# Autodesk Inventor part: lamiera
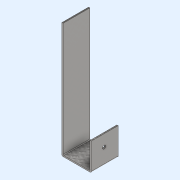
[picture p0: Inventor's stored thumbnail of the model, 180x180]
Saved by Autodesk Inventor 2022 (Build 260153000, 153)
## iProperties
Created: 2022-01
Part Number: lamiera
Material: Generico
Document SubType Name: Modeling
Designer: admin
Density: 1 g/cm^3
Appearance: Lamiera con rombi
Author: admin
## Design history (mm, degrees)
sketch "Schizzo1"
  geometry: L1 (-350, 190.785)-(-340, 200.785) reference; L2 (-350, 190.785)-(-350, -190.785) reference; L3 (-340, -200.785)-(-350, -190.785) reference; L4 (-340, -200.785)-(-290, -200.785) reference; L5 (-290, -200.785)-(-290, -100.323) reference; L6 (-290, -100.323)-(-265.5, -100.323) reference; L7 (-238.5, -73.323)-(-265.5, -100.323) reference; L8 (-238.5, -73.323)-(-238.5, 100.785) reference; L9 (-238.5, 100.785)-(-25, 100.785) reference; L10 (-25, 100.785)-(-25, -88.215) reference; L11 (-24, -89.215)-(14, -89.215) reference; L12 (15, -88.215)-(15, 25.785) reference; L13 (15, 25.785)-(90, 100.785) reference; L14 (90, 100.785)-(315, 100.785) reference; L15 (315, 100.785)-(315, -99.215) reference; L16 (315, -99.215)-(90, -99.215) reference; L17 (90, -99.215)-(90, -389.215) reference; L18 (100, -399.215)-(90, -389.215) reference; L19 (100, -399.215)-(350, -399.215) reference; L20 (350, -399.215)-(350, 200.785) reference; L21 (350, 200.785)-(-340, 200.785) reference; L22 (-25, 80.782)-(-25, -88.215); L23 (-24, -89.215)-(14, -89.215); L24 (15, -88.215)-(15, -50.215); L25 (17, -50.215)-(17, -89.218); L26 (15, -91.218)-(-25, -91.218); L27 (-27, -89.218)-(-27, 80.782); L28 (15, -38.215)-(17, -38.215); L29 (-27, 80.782)-(-25, 80.782); L30 (15, -50.215)-(17, -50.215); A1 r 1 centre (-24, -88.215) between (-25, -88.215) and (-24, -89.215) reference; A2 r 1 centre (14, -88.215) between (14, -89.215) and (15, -88.215) reference; A3 r 2 centre (-25, -89.218) between (-27, -89.218) and (-25, -91.218); A4 r 2 centre (15, -89.218) between (15, -91.218) and (17, -89.218); 1 further point
  constraints: 18 end point, 8 point on circle, 4 tangent, 2 centre point, 2 equal length, 2 perpendicular, 2 point on line, 1 equal radius
  dimensions: "d0" = 170 distance of L22.start L23.start; "d1" = 50 distance of L24.start L28.start; "d2" = 2 distance between parallel lines of L24 L25; "d3" = 2 radius of A3 (derived); "d8" = 12 distance between parallel lines of L28 L30
extrude "Estrusione1" new body sketch "Schizzo1" distance "d4" = 40; taper "d5" = 0 deg
node "Piano di lavoro1"
sketch "Schizzo2"
  geometry: C1 r 2.5 at (19, 21.903) reference; 1 further point
extrude "Estrusione2" cut sketch "Schizzo2" distance "d6" = 2; taper "d7" = 0 deg
node "Solido1"
node "Riferimento1"
node "Riferimento2"
